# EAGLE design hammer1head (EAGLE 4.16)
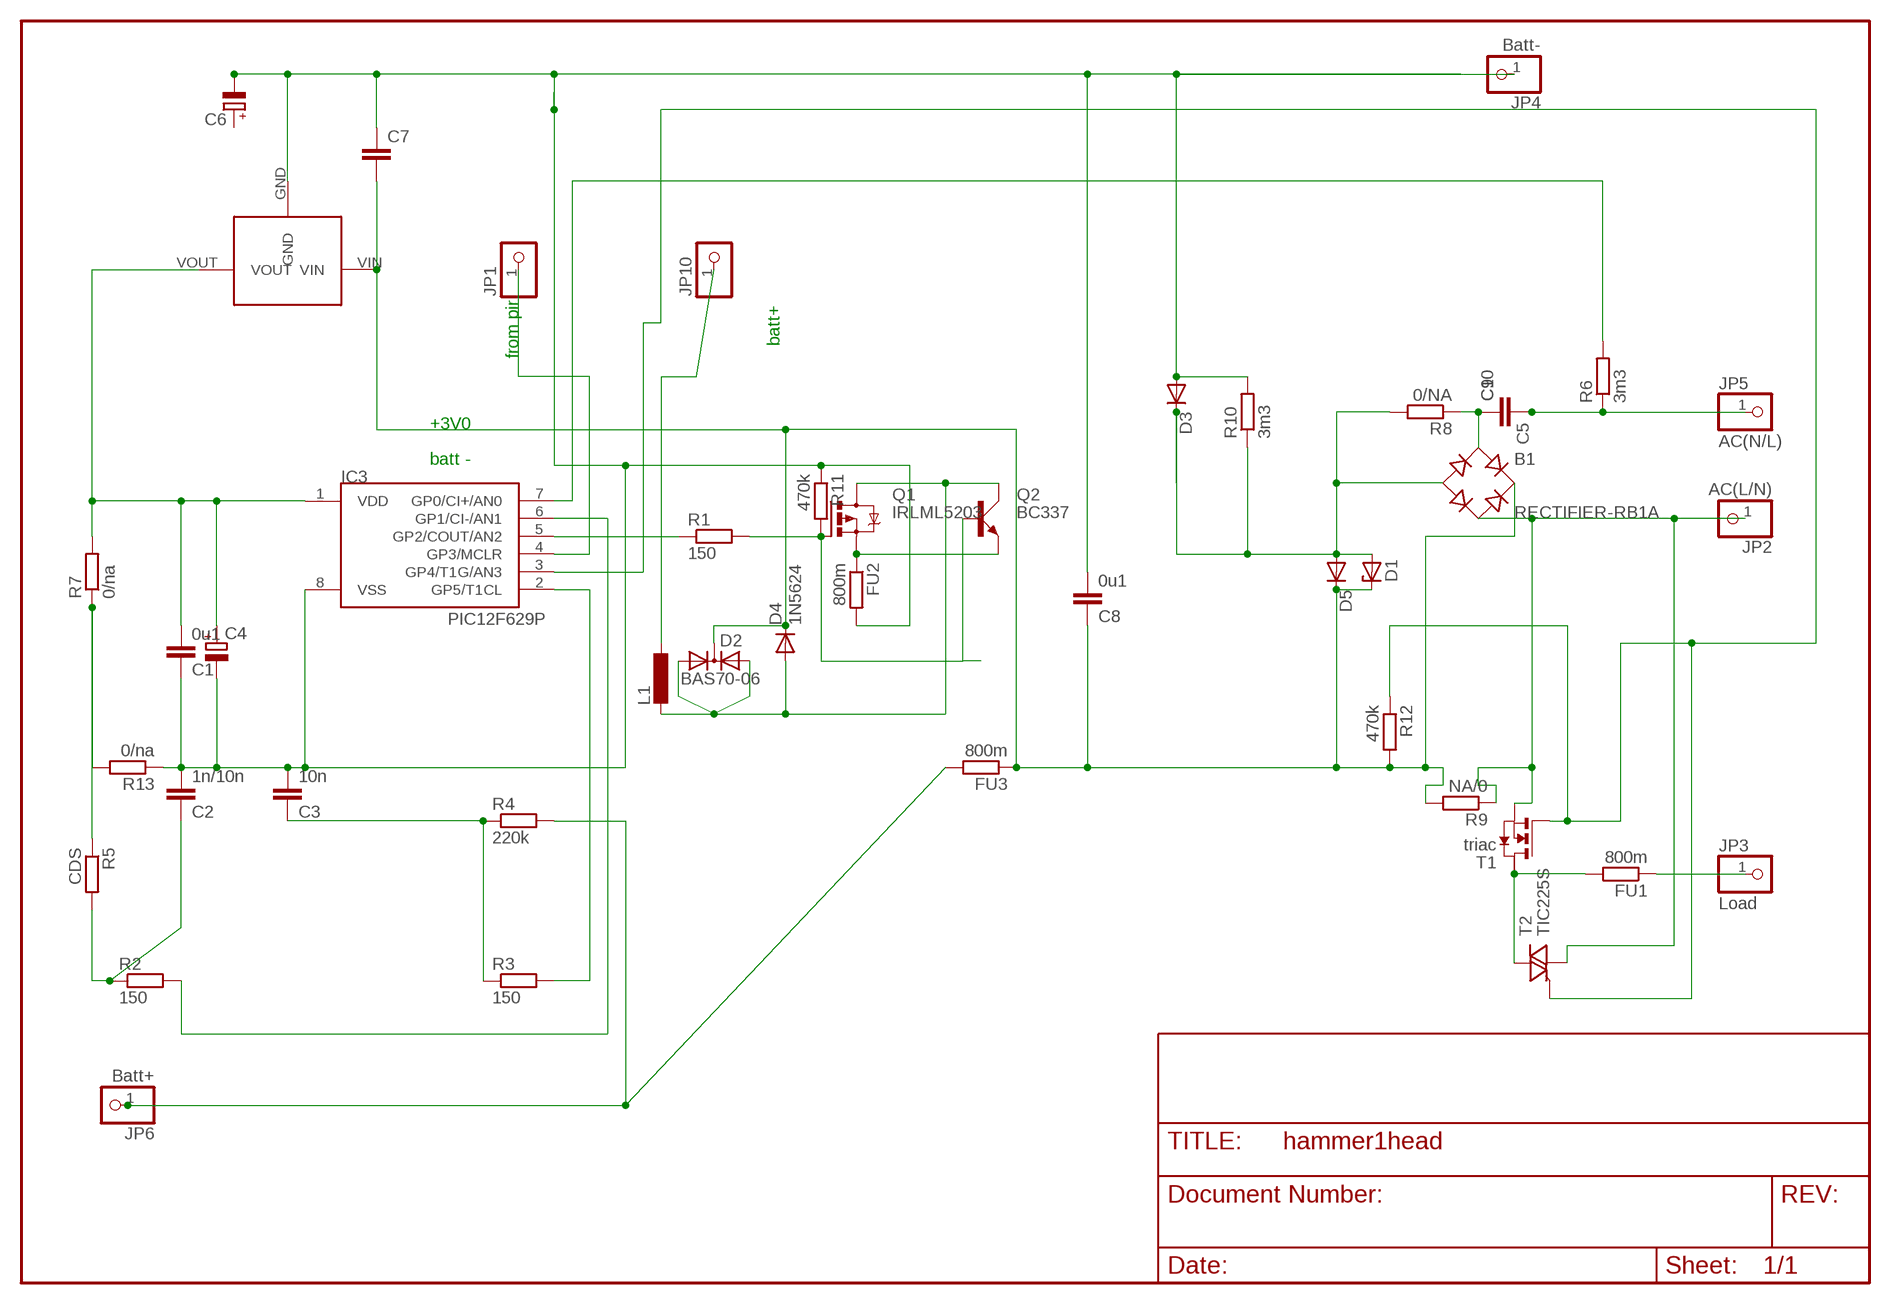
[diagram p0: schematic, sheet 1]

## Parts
B1  RECTIFIER-RB1A  [RB1A]
C1  0u1  C-EU050-024X044  [C050-024X044]
C2  1n/10n  C-EU050-024X044  [C050-024X044]
C3  10n  C-EU050-024X044  [C050-024X044]
C4  CPOL-EUE2.5-6  [E2,5-6]
C5  C-EU050-025X075  [C050-025X075]
C6  CPOL-EUE2,5-6E  [E2,5-6E]
C7  C-EU050-024X044  [C050-024X044]
C8  0u1  C-EU050-024X044  [C050-024X044]
C9  C-EU075-032X103  [C075-032X103]
C10  C-EU102-043X133  [C102-043X133]
D1  ZENER-DIODEZD-7.5  [ZDIO-7.5]
D2  BAS70-06  [SOT23]
D3  DIODE-D-7.5  [D-7.5]
D4  1N5624  [DO201-15]
D5  DIODE-D-7.5  [D-7.5]
FU1  800m  R-EU_0204/5  [0204/5]
FU2  800m  R-EU_0204/5  [0204/5]
FU3  800m  R-EU_0204/5  [0204/5]
IC3  PIC12F629P  [DIL8]
JP1  PINHD-1X1  [1X01]
JP2  AC(L/N)  PINHD-1X1  [1X01]
JP3  Load  PINHD-1X1  [1X01]
JP4  Batt-  PINHD-1X1  [1X01]
JP5  AC(N/L)  PINHD-1X1  [1X01]
JP6  Batt+  PINHD-1X1  [1X01]
JP10  PINHD-1X1  [1X01]
L1  L-EU2200-15.24  [2200-15.24]
Q1  IRLML5203  [MICRO3]
Q2  BC337  [SOT54A]
R1  150  R-EU_0204/5  [0204/5]
R2  150  R-EU_0204/5  [0204/5]
R3  150  R-EU_0204/5  [0204/5]
R4  220k  R-EU_0204/5  [0204/5]
R5  CDS  R-EU_0411/3V  [0411V]
R6  3m3  R-EU_0617/22  [0617/22]
R7  0/na  R-EU_R0402  [R0402]
R8  0/NA  R-EU_R0402  [R0402]
R9  NA/0  R-EU_R0402  [R0402]
R10  3m3  R-EU_0204/5  [0204/5]
R11  470k  R-EU_0204/5  [0204/5]
R12  470k  R-EU_0204/5  [0204/5]
R13  0/na  R-EU_R0402  [R0402]
T1  triac  NMOSSOT223  [SOT223]
T2  TIC225S  [TO220DS]
U$1  VREG-S  [TO92-S]

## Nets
GND: C1.1 C2.2 C3.2 C4.- C6.- C7.1 C8.2 D3.A FU2.2 IC3.8(VSS) JP4.1 R10.2 R11.1 R13.1 U$1.GND
N$2: IC3.6(GP1/CI-/AN1) R2.2
N$4: IC3.3(GP4/T1G/AN3) R12.1 T1.1(G) T2.G
N$5: D2.1(A1) D2.2(A2) D4.A L1.2 Q1.3(D) Q2.C
N$6: C1.2 C4.+ IC3.1(VDD) R7.2 U$1.VOUT
N$7: C3.1 R3.1 R4.1
N$8: IC3.2(GP5/T1CL) R3.2
N$9: IC3.4(GP3/MCLR) JP1.1
N$11: C2.1 R2.1 R5.2
N$12: IC3.5(GP2/COUT/AN2) R1.1
N$14: IC3.7(GP0/CI+/AN0) R6.2
N$17: JP10.1 L1.1
N$18: FU1.1 JP3.1
N$19: FU1.2 T1.2(D) T2.A2
N$20: Q1.1(G) Q2.B R1.2 R11.2
N$22: R5.1 R7.1 R13.2
N$23: B1.AC2 JP2.1 R9.1 T1.3(S) T2.A1
N$25: B1.- D1.A D3.C D5.A R8.2 R10.1
N$26: B1.AC1 C5.2 C9.1 C10.1 R8.1
N$34: FU2.1 Q1.2(S) Q2.E
N$36: FU3.2 JP6.1 R4.2
N$37: C5.1 C9.2 C10.2 JP5.1 R6.1
RECT+: B1.+ C7.2 C8.1 D1.C D2.3(C) D4.C D5.C FU3.1 R9.2 R12.2 U$1.VIN
Unconnected: C6.+ T1.4(D2)

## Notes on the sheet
- batt+
- from pir
- +3V0
- batt -

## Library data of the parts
B1 = rectifier:RECTIFIER-: Rectifier
C1-C3 C5 C8-C10 = rcl:C-EU: CAPACITOR, European symbol
C4 C6 = rcl(2):CPOL-EU: POLARIZED CAPACITOR, European symbol
C7 = rcl(2):C-EU: CAPACITOR, European symbol
D1 = diode-1:ZENER-DIODE: Z-Diode
D2 = diode-1:BAS70-06: Silicon Schottky Diodes General-purpose diode for high-speed switching
D3 D5 = diode-1:DIODE-: DIODE
D4 = diode:1N5624: DIODE
FU1-FU3 R1-R13 = rcl:R-EU_: RESISTOR, European symbol
IC3 = microchip-3:PIC12F6*: uPC nW 1k Program Flash memory 2x Timer Comparator 10b A/D converter/ 4xIN
JP1 JP10 = pinhead(2):PINHD-1X1: PIN HEADER
JP2-JP6 = pinhead:PINHD-1X1: PIN HEADER
L1 = rcl:L-EU: INDUCTOR, European symbol
Q1 = transistor-power:IRLML5203: HEXFET P-Channel Power MOSFET
Q2 = transistor-small-signal:BC337: NPN TRANSISTOR
T1 = zetex:NMOSSOT223: MOS FET
T2 = triac:TIC225S: TRIAC
U$1 = spoton:VREG-S: vreg aus spoton

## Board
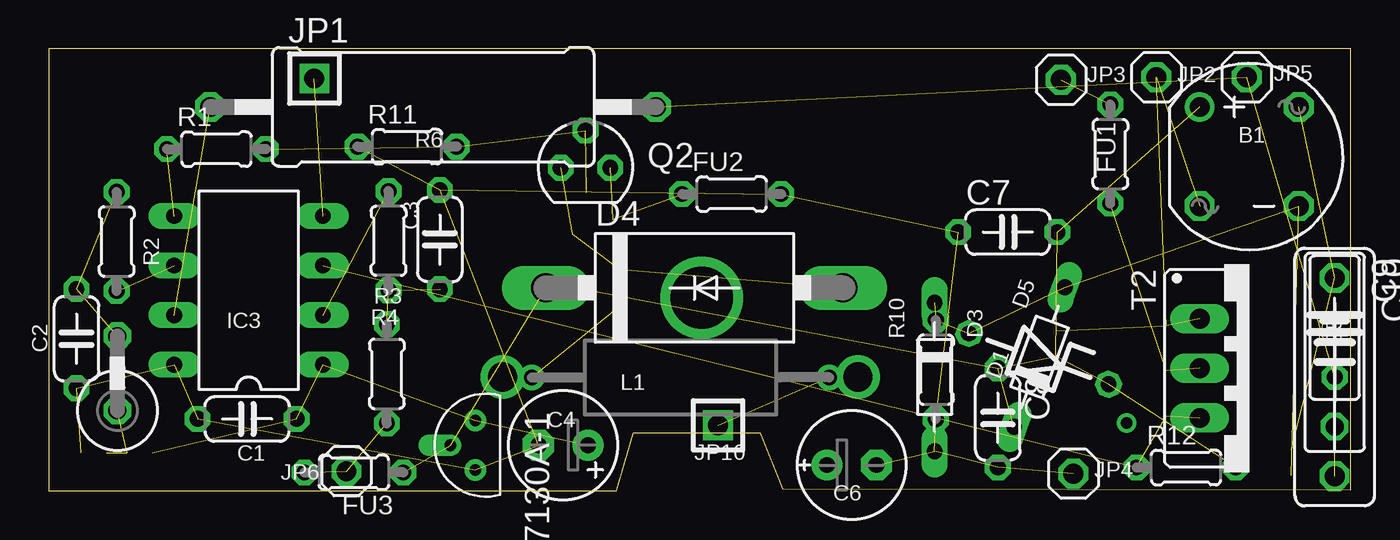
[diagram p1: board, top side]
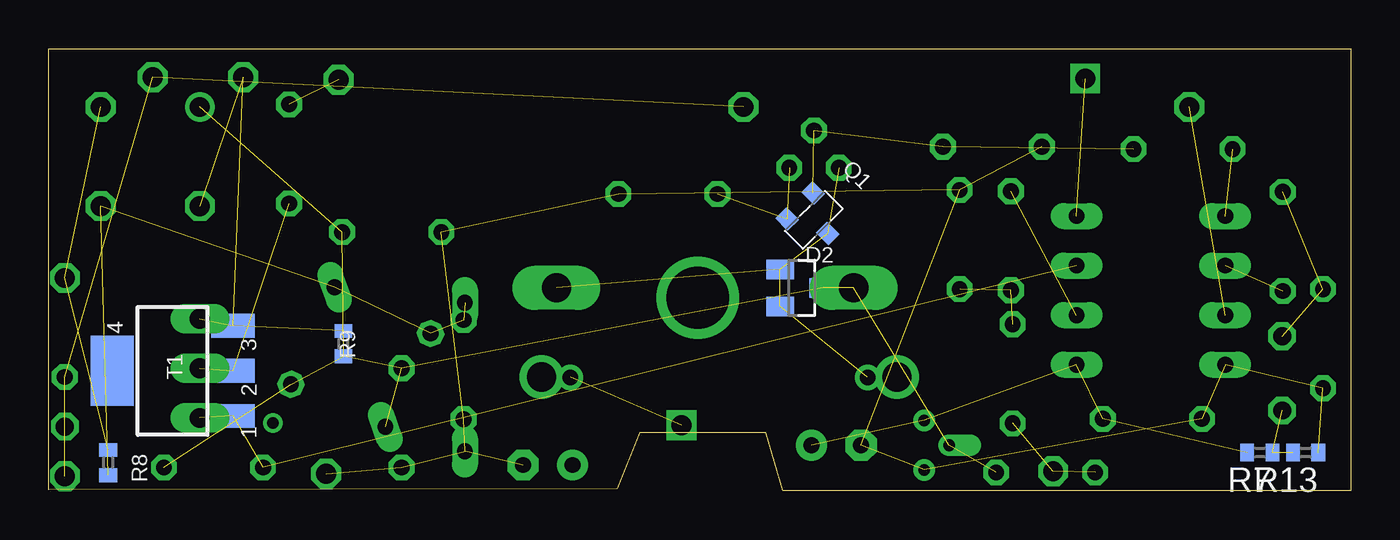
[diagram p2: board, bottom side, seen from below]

Size 66.76 x 22.66 mm. Coordinates in mm from the lower left corner, seen from the top.
Outline: 0,0 29.11,0 30,2.98 36.47,2.98 37.62,0.12 66.76,0.06 66.76,22.66 52.03,22.66 17.62,22.66 13.42,22.66 0,22.66 0,0
Copper layers (1*16): Top 0.035mm / dielectric 1.5mm / Bottom 0.035mm
Design rules "default": minimum track width 10mil, minimum drill 2mil, track to track 8mil, track to pad 8mil, pad to pad 8mil, via to via 8mil, smd to smd 8mil, copper to edge 1mil, drill to drill 8mil, minimum pad ring 10mil, minimum via ring 8mil, stop-mask expansion 4mil, vias tented up to drill 0mil, thermal gap 10mil

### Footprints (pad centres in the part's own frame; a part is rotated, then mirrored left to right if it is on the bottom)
RB1A = drill 1.016 round: + -2.54,2.54 | drill 1.016 octagon: - 2.54,-2.54; AC1 2.54,2.54; AC2 -2.54,-2.54
C050-024X044 = drill 0.813 octagon: 1 -2.54,0; 2 2.54,0
E2,5-6 = drill 0.813 pad 1.6 round: + -1.27,0 | drill 0.813 pad 1.6 octagon: - 1.27,0
C050-025X075 = drill 0.813 octagon: 1 -2.54,0; 2 2.54,0
E2,5-6E = drill 0.813 pad 1.575 round: + -1.27,0 | drill 0.813 pad 1.575 octagon: - 1.27,0
C075-032X103 = drill 0.914 octagon: 1 -3.81,0; 2 3.81,0
C102-043X133 = drill 1.016 octagon: 1 -5.08,0; 2 5.08,0
ZDIO-7.5 = drill 0.813 octagon: A 3.81,0; C -3.81,0
SOT23 = smd 1 x 1.4: 1 -0.95,-1.1; 2 0.95,-1.1; 3 0,1.1
D-7.5 = drill 0.813 long: A 3.81,0; C -3.81,0
DO201-15 = drill 1.499 long: A 7.62,0; C -7.62,0
0204/5 = drill 0.813 octagon: 1 -2.54,0; 2 2.54,0
DIL8 = drill 0.813 long: 1 -3.81,-3.81; 2 -1.27,-3.81; 3 1.27,-3.81; 4 3.81,-3.81; 5 3.81,3.81; 6 1.27,3.81; 7 -1.27,3.81; 8 -3.81,3.81
1X01 = drill 1.016 square: 1 0,0
1X01' = drill 1.016 octagon: 1 0,0
2200-15.24 = drill 0.8 pad 1.27 round: 1 -7.62,0; 2 7.62,0
MICRO3 = smd 0.8 x 0.9: 1 -0.95,-1; 2 0.95,-1; 3 0,1
SOT54A = drill 0.813 octagon: B 0,1.905; C -1.27,0; E 1.27,0
0411V = drill 0.914 octagon: 1 -2.54,0; 2 1.27,0
0617/22 = drill 1.016 octagon: 1 -11.43,0; 2 11.43,0
R0402 = smd 0.7 x 0.9: 1 -0.65,0; 2 0.65,0
SOT223 = smd 1.219 x 2.235: 1 -2.311,-3.099; 2 0,-3.099; 3 2.311,-3.099 | smd 3.6 x 2.2: 4 0,3.099
TO220DS = drill 1.016 long: A1 -2.54,-2.54; A2 0,-2.54; G 2.54,-2.54
TO92-S = drill 0.6 round: GND -2.54,0; VOUT 0,0 | drill 0.6 offset: VIN -1.27,1.27

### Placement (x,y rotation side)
B1  61.56,17.14 0 top
C1  10.17,3.69 0 top
C2  1.42,7.81 270 top
C3  20.05,12.89 90 top
C4  26.38,2.34 180 top
C5  65.94,8.38 90 top
C6  41.17,1.33 0 top
C7  49.17,13.27 0 top
C8  48.67,3.74 270 top
C9  65.94,7.11 270 top
C10  65.94,5.84 270 top
D1  50.77,6.77 160 top
D2  28.16,10.41 270 bottom
D3  45.43,5.84 270 top
D4  33.11,10.41 0 top
D5  50.8,6.86 70 top
FU1  54.43,17.27 270 top
FU2  35.01,15.22 0 top
FU3  15.65,0.95 180 top
IC3  10.25,10.28 90 top
JP1  13.61,21.14 0 top
JP2  AC(L/N)  [1X01']  56.79,21.2 0 top
JP3  Load  [1X01']  51.91,21.08 0 top
JP4  Batt-  [1X01']  52.54,0.88 0 top
JP5  AC(N/L)  [1X01']  61.43,21.2 0 top
JP6  Batt+  [1X01']  15.27,1.01 0 top
JP10  34.32,3.36 0 top
L1  32.4,5.82 180 top
Q1  27.53,13.89 225 bottom
Q2  27.52,16.57 0 top
R1  8.6,17.52 0 top
R2  3.48,12.79 270 top
R3  17.42,12.82 90 top
R4  17.33,6 270 top
R5  3.52,6.66 90 top
R6  19.71,19.68 180 top
R7  4.66,1.96 180 bottom
R8  63.72,1.46 270 bottom
R9  51.65,7.55 270 bottom
R10  45.49,6.22 270 top
R11  18.38,17.65 0 top
R12  58.32,1.2 0 top
R13  2.31,1.96 180 bottom
T1  60.41,6.15 90 bottom
T2  61.56,6.28 270 top
U$1  21.87,3.61 90 top

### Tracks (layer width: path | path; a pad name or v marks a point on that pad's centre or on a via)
GND  (14 unrouted)
N$2  (1 unrouted)
N$3  (via drill 0.6)
  other vias: 55.27,3.49
N$4  (3 unrouted)
N$5  (5 unrouted)
N$6  (4 unrouted)
N$7  (2 unrouted)
N$8  (1 unrouted)
N$9  (1 unrouted)
N$11  (2 unrouted)
N$12  (1 unrouted)
N$14  (1 unrouted)
N$15  (via drill 1.5)
  other vias: 41.49,5.84
N$16  (via drill 1.5)
  other vias: 23.27,5.84
N$17  (1 unrouted)
N$18  (1 unrouted)
N$19  (2 unrouted)
N$20  (3 unrouted)
N$22  (2 unrouted)
N$23  (4 unrouted)
N$25  (5 unrouted)
N$26  (2 unrouted)
N$28  (via drill 3.2)
  other vias: 33.49,9.9
N$34  (2 unrouted)
N$36  (2 unrouted)
N$37  (4 unrouted)
RECT+  (10 unrouted)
